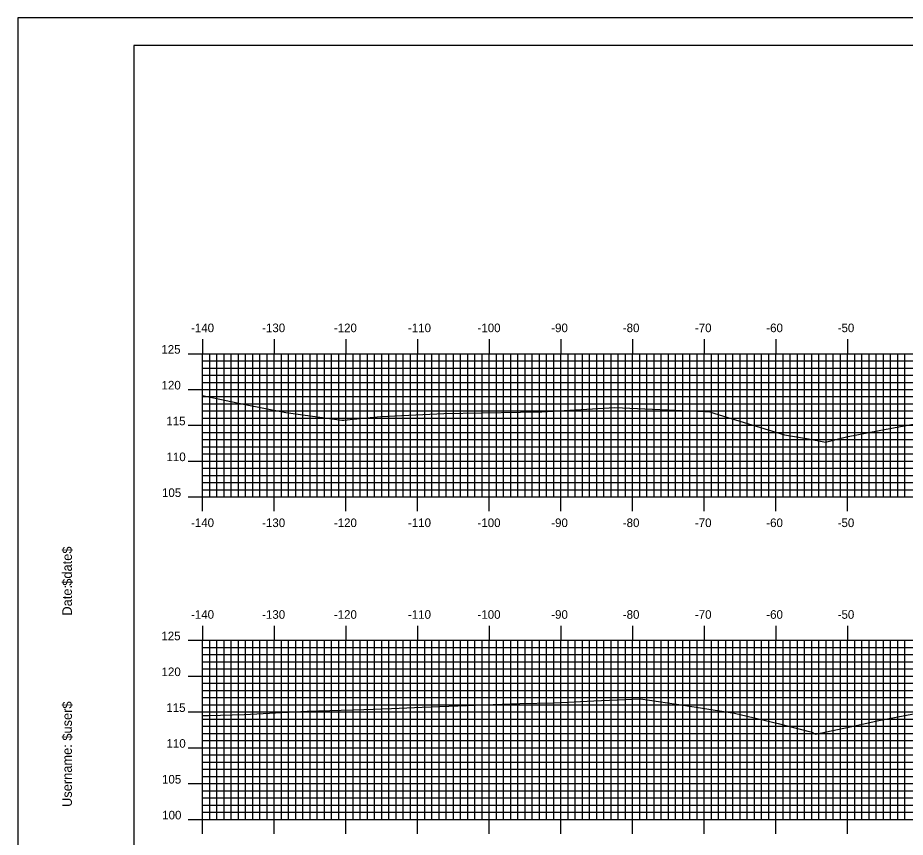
# Model space of a CAD drawing. Extents: x 1685586 to 1685929, y 461260 to 461480.
# Drawn here: x 1685586 to 1685709.8, y 461365.6 to 461480 of the extents above; entities that cross this region are included whole.
import ezdxf

# ---------------------------------------------------------------- set-up
doc = ezdxf.new("R2010")
doc.units = 0
for name, color, linetype in [('BORDER', 7, 'Continuous'), ('H_V ANNOTATION', 7, 'Continuous'), ('MAJOR', 7, 'Continuous'), ('MINOR', 7, 'Continuous'), ('PLOT BOUNDARY', 7, 'Continuous'), ('S_Roadway_Centerline', 7, 'Continuous')]:
    doc.layers.add(name, color=color, linetype=linetype)

msp = doc.modelspace()

# ---------------------------------------------------------------- linework, layer by layer
at = {"layer": 'BORDER'}
msp.add_lwpolyline([(1685602.14, 461266.07), (1685922.14, 461266.07), (1685922.14, 461476.07), (1685602.14, 461476.07)], close=True, dxfattribs=at)
at = {"layer": 'MAJOR'}
for p, q in [((1685611.74, 461435.08), (1685611.74, 461433.07)), ((1685621.74, 461435.08), (1685621.74, 461433.07)), ((1685631.74, 461435.08), (1685631.74, 461433.07)), ((1685641.74, 461435.08), (1685641.74, 461433.07)), ((1685651.74, 461435.08), (1685651.74, 461433.07)), ((1685661.74, 461435.08), (1685661.74, 461433.07)), ((1685671.74, 461435.08), (1685671.74, 461433.07)), ((1685681.74, 461435.08), (1685681.74, 461433.07)), ((1685691.74, 461435.08), (1685691.74, 461433.07)), ((1685701.74, 461435.08), (1685701.74, 461433.07)), ((1685609.74, 461433.07), (1685611.74, 461433.07)), ((1685611.74, 461433.07), (1685891.74, 461433.07)), ((1685611.74, 461413.07), (1685611.74, 461433.07)), ((1685611.74, 461413.07), (1685611.74, 461433.07)), ((1685611.74, 461433.07), (1685891.74, 461433.07)), ((1685621.74, 461413.07), (1685621.74, 461433.07)), ((1685631.74, 461413.07), (1685631.74, 461433.07)), ((1685641.74, 461413.07), (1685641.74, 461433.07)), ((1685651.74, 461413.07), (1685651.74, 461433.07)), ((1685661.74, 461413.07), (1685661.74, 461433.07)), ((1685671.74, 461413.07), (1685671.74, 461433.07)), ((1685681.74, 461413.07), (1685681.74, 461433.07)), ((1685691.74, 461413.07), (1685691.74, 461433.07)), ((1685701.74, 461413.07), (1685701.74, 461433.07)), ((1685609.74, 461428.07), (1685611.74, 461428.07)), ((1685611.74, 461428.07), (1685891.74, 461428.07)), ((1685609.74, 461423.07), (1685611.74, 461423.07)), ((1685611.74, 461423.07), (1685891.74, 461423.07)), ((1685609.74, 461418.07), (1685611.74, 461418.07)), ((1685611.74, 461418.07), (1685891.74, 461418.07)), ((1685609.74, 461413.07), (1685611.74, 461413.07)), ((1685611.74, 461413.07), (1685891.74, 461413.07)), ((1685611.74, 461413.07), (1685891.74, 461413.07)), ((1685611.74, 461411.07), (1685611.74, 461413.07)), ((1685621.74, 461411.07), (1685621.74, 461413.07)), ((1685631.74, 461411.07), (1685631.74, 461413.07)), ((1685641.74, 461411.07), (1685641.74, 461413.07)), ((1685651.74, 461411.07), (1685651.74, 461413.07)), ((1685661.74, 461411.07), (1685661.74, 461413.07)), ((1685671.74, 461411.07), (1685671.74, 461413.07)), ((1685681.74, 461411.07), (1685681.74, 461413.07)), ((1685691.74, 461411.07), (1685691.74, 461413.07)), ((1685701.74, 461411.07), (1685701.74, 461413.07)), ((1685611.74, 461395.08), (1685611.74, 461393.07)), ((1685621.74, 461395.08), (1685621.74, 461393.07)), ((1685631.74, 461395.08), (1685631.74, 461393.07)), ((1685641.74, 461395.08), (1685641.74, 461393.07)), ((1685651.74, 461395.08), (1685651.74, 461393.07)), ((1685661.74, 461395.08), (1685661.74, 461393.07)), ((1685671.74, 461395.08), (1685671.74, 461393.07)), ((1685681.74, 461395.08), (1685681.74, 461393.07)), ((1685691.74, 461395.08), (1685691.74, 461393.07)), ((1685701.74, 461395.08), (1685701.74, 461393.07)), ((1685609.74, 461393.07), (1685611.74, 461393.07)), ((1685611.74, 461393.07), (1685891.74, 461393.07)), ((1685611.74, 461368.07), (1685611.74, 461393.07)), ((1685611.74, 461368.07), (1685611.74, 461393.07)), ((1685611.74, 461393.07), (1685891.74, 461393.07)), ((1685621.74, 461368.07), (1685621.74, 461393.07)), ((1685631.74, 461368.07), (1685631.74, 461393.07)), ((1685641.74, 461368.07), (1685641.74, 461393.07)), ((1685651.74, 461368.07), (1685651.74, 461393.07)), ((1685661.74, 461368.07), (1685661.74, 461393.07)), ((1685671.74, 461368.07), (1685671.74, 461393.07)), ((1685681.74, 461368.07), (1685681.74, 461393.07)), ((1685691.74, 461368.07), (1685691.74, 461393.07)), ((1685701.74, 461368.07), (1685701.74, 461393.07)), ((1685609.74, 461388.07), (1685611.74, 461388.07)), ((1685611.74, 461388.07), (1685891.74, 461388.07)), ((1685609.74, 461383.07), (1685611.74, 461383.07)), ((1685611.74, 461383.07), (1685891.74, 461383.07)), ((1685609.74, 461378.07), (1685611.74, 461378.07)), ((1685611.74, 461378.07), (1685891.74, 461378.07)), ((1685609.74, 461373.07), (1685611.74, 461373.07)), ((1685611.74, 461373.07), (1685891.74, 461373.07)), ((1685609.74, 461368.07), (1685611.74, 461368.07)), ((1685611.74, 461368.07), (1685891.74, 461368.07)), ((1685611.74, 461368.07), (1685891.74, 461368.07)), ((1685611.74, 461366.07), (1685611.74, 461368.07)), ((1685621.74, 461366.07), (1685621.74, 461368.07)), ((1685631.74, 461366.07), (1685631.74, 461368.07)), ((1685641.74, 461366.07), (1685641.74, 461368.07)), ((1685651.74, 461366.07), (1685651.74, 461368.07)), ((1685661.74, 461366.07), (1685661.74, 461368.07)), ((1685671.74, 461366.07), (1685671.74, 461368.07)), ((1685681.74, 461366.07), (1685681.74, 461368.07)), ((1685691.74, 461366.07), (1685691.74, 461368.07)), ((1685701.74, 461366.07), (1685701.74, 461368.07))]:
    msp.add_line(p, q, dxfattribs=at)
at = {"layer": 'MINOR'}
for p, q in [((1685612.74, 461413.07), (1685612.74, 461433.07)), ((1685613.74, 461413.07), (1685613.74, 461433.07)), ((1685614.74, 461413.07), (1685614.74, 461433.07)), ((1685615.74, 461413.07), (1685615.74, 461433.07)), ((1685616.74, 461413.07), (1685616.74, 461433.07)), ((1685617.74, 461413.07), (1685617.74, 461433.07)), ((1685618.74, 461413.07), (1685618.74, 461433.07)), ((1685619.74, 461413.07), (1685619.74, 461433.07)), ((1685620.74, 461413.07), (1685620.74, 461433.07)), ((1685622.74, 461413.07), (1685622.74, 461433.07)), ((1685623.74, 461413.07), (1685623.74, 461433.07)), ((1685624.74, 461413.07), (1685624.74, 461433.07)), ((1685625.74, 461413.07), (1685625.74, 461433.07)), ((1685626.74, 461413.07), (1685626.74, 461433.07)), ((1685627.74, 461413.07), (1685627.74, 461433.07)), ((1685628.74, 461413.07), (1685628.74, 461433.07)), ((1685629.74, 461413.07), (1685629.74, 461433.07)), ((1685630.74, 461413.07), (1685630.74, 461433.07)), ((1685632.74, 461413.07), (1685632.74, 461433.07)), ((1685633.74, 461413.07), (1685633.74, 461433.07)), ((1685634.74, 461413.07), (1685634.74, 461433.07)), ((1685635.74, 461413.07), (1685635.74, 461433.07)), ((1685636.74, 461413.07), (1685636.74, 461433.07)), ((1685637.74, 461413.07), (1685637.74, 461433.07)), ((1685638.74, 461413.07), (1685638.74, 461433.07)), ((1685639.74, 461413.07), (1685639.74, 461433.07)), ((1685640.74, 461413.07), (1685640.74, 461433.07)), ((1685642.74, 461413.07), (1685642.74, 461433.07)), ((1685643.74, 461413.07), (1685643.74, 461433.07)), ((1685644.74, 461413.07), (1685644.74, 461433.07)), ((1685645.74, 461413.07), (1685645.74, 461433.07)), ((1685646.74, 461413.07), (1685646.74, 461433.07)), ((1685647.74, 461413.07), (1685647.74, 461433.07)), ((1685648.74, 461413.07), (1685648.74, 461433.07)), ((1685649.74, 461413.07), (1685649.74, 461433.07)), ((1685650.74, 461413.07), (1685650.74, 461433.07)), ((1685652.74, 461413.07), (1685652.74, 461433.07)), ((1685653.74, 461413.07), (1685653.74, 461433.07)), ((1685654.74, 461413.07), (1685654.74, 461433.07)), ((1685655.74, 461413.07), (1685655.74, 461433.07)), ((1685656.74, 461413.07), (1685656.74, 461433.07)), ((1685657.74, 461413.07), (1685657.74, 461433.07)), ((1685658.74, 461413.07), (1685658.74, 461433.07)), ((1685659.74, 461413.07), (1685659.74, 461433.07)), ((1685660.74, 461413.07), (1685660.74, 461433.07)), ((1685662.74, 461413.07), (1685662.74, 461433.07)), ((1685663.74, 461413.07), (1685663.74, 461433.07)), ((1685664.74, 461413.07), (1685664.74, 461433.07)), ((1685665.74, 461413.07), (1685665.74, 461433.07)), ((1685666.74, 461413.07), (1685666.74, 461433.07)), ((1685667.74, 461413.07), (1685667.74, 461433.07)), ((1685668.74, 461413.07), (1685668.74, 461433.07)), ((1685669.74, 461413.07), (1685669.74, 461433.07)), ((1685670.74, 461413.07), (1685670.74, 461433.07)), ((1685672.74, 461413.07), (1685672.74, 461433.07)), ((1685673.74, 461413.07), (1685673.74, 461433.07)), ((1685674.74, 461413.07), (1685674.74, 461433.07)), ((1685675.74, 461413.07), (1685675.74, 461433.07)), ((1685676.74, 461413.07), (1685676.74, 461433.07)), ((1685677.74, 461413.07), (1685677.74, 461433.07)), ((1685678.74, 461413.07), (1685678.74, 461433.07)), ((1685679.74, 461413.07), (1685679.74, 461433.07)), ((1685680.74, 461413.07), (1685680.74, 461433.07)), ((1685682.74, 461413.07), (1685682.74, 461433.07)), ((1685683.74, 461413.07), (1685683.74, 461433.07)), ((1685684.74, 461413.07), (1685684.74, 461433.07)), ((1685685.74, 461413.07), (1685685.74, 461433.07)), ((1685686.74, 461413.07), (1685686.74, 461433.07)), ((1685687.74, 461413.07), (1685687.74, 461433.07)), ((1685688.74, 461413.07), (1685688.74, 461433.07)), ((1685689.74, 461413.07), (1685689.74, 461433.07)), ((1685690.74, 461413.07), (1685690.74, 461433.07)), ((1685692.74, 461413.07), (1685692.74, 461433.07)), ((1685693.74, 461413.07), (1685693.74, 461433.07)), ((1685694.74, 461413.07), (1685694.74, 461433.07)), ((1685695.74, 461413.07), (1685695.74, 461433.07)), ((1685696.74, 461413.07), (1685696.74, 461433.07)), ((1685697.74, 461413.07), (1685697.74, 461433.07)), ((1685698.74, 461413.07), (1685698.74, 461433.07)), ((1685699.74, 461413.07), (1685699.74, 461433.07)), ((1685700.74, 461413.07), (1685700.74, 461433.07)), ((1685702.74, 461413.07), (1685702.74, 461433.07)), ((1685703.74, 461413.07), (1685703.74, 461433.07)), ((1685704.74, 461413.07), (1685704.74, 461433.07)), ((1685705.74, 461413.07), (1685705.74, 461433.07)), ((1685706.74, 461413.07), (1685706.74, 461433.07)), ((1685707.74, 461413.07), (1685707.74, 461433.07)), ((1685708.74, 461413.07), (1685708.74, 461433.07)), ((1685709.74, 461413.07), (1685709.74, 461433.07)), ((1685611.74, 461432.07), (1685891.74, 461432.07)), ((1685611.74, 461432.07), (1685613.75, 461432.07)), ((1685611.74, 461431.07), (1685891.74, 461431.07)), ((1685611.74, 461431.07), (1685613.75, 461431.07)), ((1685611.74, 461430.07), (1685891.74, 461430.07)), ((1685611.74, 461430.07), (1685613.75, 461430.07)), ((1685611.74, 461429.07), (1685891.74, 461429.07)), ((1685611.74, 461429.07), (1685613.75, 461429.07)), ((1685611.74, 461427.07), (1685891.74, 461427.07)), ((1685611.74, 461427.07), (1685613.75, 461427.07)), ((1685611.74, 461426.07), (1685891.74, 461426.07)), ((1685611.74, 461426.07), (1685613.75, 461426.07)), ((1685611.74, 461425.07), (1685891.74, 461425.07)), ((1685611.74, 461425.07), (1685613.75, 461425.07)), ((1685611.74, 461424.07), (1685891.74, 461424.07)), ((1685611.74, 461424.07), (1685613.75, 461424.07)), ((1685611.74, 461422.07), (1685891.74, 461422.07)), ((1685611.74, 461422.07), (1685613.75, 461422.07)), ((1685611.74, 461421.07), (1685891.74, 461421.07)), ((1685611.74, 461421.07), (1685613.75, 461421.07)), ((1685611.74, 461420.07), (1685891.74, 461420.07)), ((1685611.74, 461420.07), (1685613.75, 461420.07)), ((1685611.74, 461419.07), (1685891.74, 461419.07)), ((1685611.74, 461419.07), (1685613.75, 461419.07)), ((1685611.74, 461417.07), (1685891.74, 461417.07)), ((1685611.74, 461417.07), (1685613.75, 461417.07)), ((1685611.74, 461416.07), (1685891.74, 461416.07)), ((1685611.74, 461416.07), (1685613.75, 461416.07)), ((1685611.74, 461415.07), (1685891.74, 461415.07)), ((1685611.74, 461415.07), (1685613.75, 461415.07)), ((1685611.74, 461414.07), (1685891.74, 461414.07)), ((1685611.74, 461414.07), (1685613.75, 461414.07)), ((1685612.74, 461368.07), (1685612.74, 461393.07)), ((1685613.74, 461368.07), (1685613.74, 461393.07)), ((1685614.74, 461368.07), (1685614.74, 461393.07)), ((1685615.74, 461368.07), (1685615.74, 461393.07)), ((1685616.74, 461368.07), (1685616.74, 461393.07)), ((1685617.74, 461368.07), (1685617.74, 461393.07)), ((1685618.74, 461368.07), (1685618.74, 461393.07)), ((1685619.74, 461368.07), (1685619.74, 461393.07)), ((1685620.74, 461368.07), (1685620.74, 461393.07)), ((1685622.74, 461368.07), (1685622.74, 461393.07)), ((1685623.74, 461368.07), (1685623.74, 461393.07)), ((1685624.74, 461368.07), (1685624.74, 461393.07)), ((1685625.74, 461368.07), (1685625.74, 461393.07)), ((1685626.74, 461368.07), (1685626.74, 461393.07)), ((1685627.74, 461368.07), (1685627.74, 461393.07)), ((1685628.74, 461368.07), (1685628.74, 461393.07)), ((1685629.74, 461368.07), (1685629.74, 461393.07)), ((1685630.74, 461368.07), (1685630.74, 461393.07)), ((1685632.74, 461368.07), (1685632.74, 461393.07)), ((1685633.74, 461368.07), (1685633.74, 461393.07)), ((1685634.74, 461368.07), (1685634.74, 461393.07)), ((1685635.74, 461368.07), (1685635.74, 461393.07)), ((1685636.74, 461368.07), (1685636.74, 461393.07)), ((1685637.74, 461368.07), (1685637.74, 461393.07)), ((1685638.74, 461368.07), (1685638.74, 461393.07)), ((1685639.74, 461368.07), (1685639.74, 461393.07)), ((1685640.74, 461368.07), (1685640.74, 461393.07)), ((1685642.74, 461368.07), (1685642.74, 461393.07)), ((1685643.74, 461368.07), (1685643.74, 461393.07)), ((1685644.74, 461368.07), (1685644.74, 461393.07)), ((1685645.74, 461368.07), (1685645.74, 461393.07)), ((1685646.74, 461368.07), (1685646.74, 461393.07)), ((1685647.74, 461368.07), (1685647.74, 461393.07)), ((1685648.74, 461368.07), (1685648.74, 461393.07)), ((1685649.74, 461368.07), (1685649.74, 461393.07)), ((1685650.74, 461368.07), (1685650.74, 461393.07)), ((1685652.74, 461368.07), (1685652.74, 461393.07)), ((1685653.74, 461368.07), (1685653.74, 461393.07)), ((1685654.74, 461368.07), (1685654.74, 461393.07)), ((1685655.74, 461368.07), (1685655.74, 461393.07)), ((1685656.74, 461368.07), (1685656.74, 461393.07)), ((1685657.74, 461368.07), (1685657.74, 461393.07)), ((1685658.74, 461368.07), (1685658.74, 461393.07)), ((1685659.74, 461368.07), (1685659.74, 461393.07)), ((1685660.74, 461368.07), (1685660.74, 461393.07)), ((1685662.74, 461368.07), (1685662.74, 461393.07)), ((1685663.74, 461368.07), (1685663.74, 461393.07)), ((1685664.74, 461368.07), (1685664.74, 461393.07)), ((1685665.74, 461368.07), (1685665.74, 461393.07)), ((1685666.74, 461368.07), (1685666.74, 461393.07)), ((1685667.74, 461368.07), (1685667.74, 461393.07)), ((1685668.74, 461368.07), (1685668.74, 461393.07)), ((1685669.74, 461368.07), (1685669.74, 461393.07)), ((1685670.74, 461368.07), (1685670.74, 461393.07)), ((1685672.74, 461368.07), (1685672.74, 461393.07)), ((1685673.74, 461368.07), (1685673.74, 461393.07)), ((1685674.74, 461368.07), (1685674.74, 461393.07)), ((1685675.74, 461368.07), (1685675.74, 461393.07)), ((1685676.74, 461368.07), (1685676.74, 461393.07)), ((1685677.74, 461368.07), (1685677.74, 461393.07)), ((1685678.74, 461368.07), (1685678.74, 461393.07)), ((1685679.74, 461368.07), (1685679.74, 461393.07)), ((1685680.74, 461368.07), (1685680.74, 461393.07)), ((1685682.74, 461368.07), (1685682.74, 461393.07)), ((1685683.74, 461368.07), (1685683.74, 461393.07)), ((1685684.74, 461368.07), (1685684.74, 461393.07)), ((1685685.74, 461368.07), (1685685.74, 461393.07)), ((1685686.74, 461368.07), (1685686.74, 461393.07)), ((1685687.74, 461368.07), (1685687.74, 461393.07)), ((1685688.74, 461368.07), (1685688.74, 461393.07)), ((1685689.74, 461368.07), (1685689.74, 461393.07)), ((1685690.74, 461368.07), (1685690.74, 461393.07)), ((1685692.74, 461368.07), (1685692.74, 461393.07)), ((1685693.74, 461368.07), (1685693.74, 461393.07)), ((1685694.74, 461368.07), (1685694.74, 461393.07)), ((1685695.74, 461368.07), (1685695.74, 461393.07)), ((1685696.74, 461368.07), (1685696.74, 461393.07)), ((1685697.74, 461368.07), (1685697.74, 461393.07)), ((1685698.74, 461368.07), (1685698.74, 461393.07)), ((1685699.74, 461368.07), (1685699.74, 461393.07)), ((1685700.74, 461368.07), (1685700.74, 461393.07)), ((1685702.74, 461368.07), (1685702.74, 461393.07)), ((1685703.74, 461368.07), (1685703.74, 461393.07)), ((1685704.74, 461368.07), (1685704.74, 461393.07)), ((1685705.74, 461368.07), (1685705.74, 461393.07)), ((1685706.74, 461368.07), (1685706.74, 461393.07)), ((1685707.74, 461368.07), (1685707.74, 461393.07)), ((1685708.74, 461368.07), (1685708.74, 461393.07)), ((1685709.74, 461368.07), (1685709.74, 461393.07)), ((1685611.74, 461392.07), (1685891.74, 461392.07)), ((1685611.74, 461392.07), (1685613.75, 461392.07)), ((1685611.74, 461391.07), (1685891.74, 461391.07)), ((1685611.74, 461391.07), (1685613.75, 461391.07)), ((1685611.74, 461390.07), (1685891.74, 461390.07)), ((1685611.74, 461390.07), (1685613.75, 461390.07)), ((1685611.74, 461389.07), (1685891.74, 461389.07)), ((1685611.74, 461389.07), (1685613.75, 461389.07)), ((1685611.74, 461387.07), (1685891.74, 461387.07)), ((1685611.74, 461387.07), (1685613.75, 461387.07)), ((1685611.74, 461386.07), (1685891.74, 461386.07)), ((1685611.74, 461386.07), (1685613.75, 461386.07)), ((1685611.74, 461385.07), (1685891.74, 461385.07)), ((1685611.74, 461385.07), (1685613.75, 461385.07)), ((1685611.74, 461384.07), (1685891.74, 461384.07)), ((1685611.74, 461384.07), (1685613.75, 461384.07)), ((1685611.74, 461382.07), (1685891.74, 461382.07)), ((1685611.74, 461382.07), (1685613.75, 461382.07)), ((1685611.74, 461381.07), (1685891.74, 461381.07)), ((1685611.74, 461381.07), (1685613.75, 461381.07)), ((1685611.74, 461380.07), (1685891.74, 461380.07)), ((1685611.74, 461380.07), (1685613.75, 461380.07)), ((1685611.74, 461379.07), (1685891.74, 461379.07)), ((1685611.74, 461379.07), (1685613.75, 461379.07)), ((1685611.74, 461377.07), (1685891.74, 461377.07)), ((1685611.74, 461377.07), (1685613.75, 461377.07)), ((1685611.74, 461376.07), (1685891.74, 461376.07)), ((1685611.74, 461376.07), (1685613.75, 461376.07)), ((1685611.74, 461375.07), (1685891.74, 461375.07)), ((1685611.74, 461375.07), (1685613.75, 461375.07)), ((1685611.74, 461374.07), (1685891.74, 461374.07)), ((1685611.74, 461374.07), (1685613.75, 461374.07)), ((1685611.74, 461372.07), (1685891.74, 461372.07)), ((1685611.74, 461372.07), (1685613.75, 461372.07)), ((1685611.74, 461371.07), (1685891.74, 461371.07)), ((1685611.74, 461371.07), (1685613.75, 461371.07)), ((1685611.74, 461370.07), (1685891.74, 461370.07)), ((1685611.74, 461370.07), (1685613.75, 461370.07)), ((1685611.74, 461369.07), (1685891.74, 461369.07)), ((1685611.74, 461369.07), (1685613.75, 461369.07))]:
    msp.add_line(p, q, dxfattribs=at)
at = {"layer": 'PLOT BOUNDARY'}
msp.add_lwpolyline([(1685585.96, 461259.95), (1685925.96, 461259.95), (1685925.96, 461479.95), (1685585.96, 461479.95)], close=True, dxfattribs=at)
at = {"layer": 'S_Roadway_Centerline'}
for points in [[(1685611.74, 461427.25), (1685617.45, 461426.01), (1685623.36, 461424.87), (1685631.18, 461423.8), (1685631.47, 461423.81), (1685634.16, 461424.06), (1685636.63, 461424.28), (1685645.4, 461424.73), (1685656.09, 461424.9), (1685657.75, 461424.94), (1685659.07, 461424.97), (1685669.28, 461425.55), (1685681.85, 461424.99), (1685682.52, 461424.94), (1685683.2, 461424.74), (1685692.94, 461421.74), (1685696.27, 461421.17), (1685698.67, 461420.72), (1685701.58, 461421.45), (1685706.16, 461422.36), (1685717.62, 461424.47)], [(1685611.74, 461382.55), (1685612.56, 461382.58), (1685617.54, 461382.73), (1685626.33, 461383.19), (1685634.25, 461383.39), (1685638.12, 461383.53), (1685642.4, 461383.74), (1685656, 461384.25), (1685660.81, 461384.36), (1685666.34, 461384.62), (1685672.82, 461384.89), (1685679.12, 461383.99), (1685685.95, 461382.92), (1685692.05, 461381.47), (1685696.18, 461380.39), (1685696.63, 461380.29), (1685697.26, 461379.98), (1685702.74, 461381.15), (1685705.87, 461381.82), (1685710.94, 461382.8)]]:
    msp.add_lwpolyline(points, dxfattribs=at)

# ---------------------------------------------------------------- texts
at = {"layer": 'BORDER'}
for s, p in [('$date$', (1685593.51, 461400.68)), ('Date:', (1685593.51, 461396.51)), ('$user$', (1685593.51, 461379.06)), ('Username:', (1685593.51, 461369.81))]:
    msp.add_text(s, height=1.339, rotation=90, dxfattribs=at).set_placement(p)
at = {"layer": 'H_V ANNOTATION'}
for s, p in [('-140', (1685610.13, 461436.07)), ('-130', (1685620.05, 461436.07)), ('-120', (1685630.06, 461436.07)), ('-110', (1685640.4, 461436.07)), ('-100', (1685650.1, 461436.07)), ('-90', (1685660.39, 461436.07)), ('-80', (1685670.37, 461436.07)), ('-70', (1685680.43, 461436.07)), ('-60', (1685690.39, 461436.07)), ('-50', (1685700.35, 461436.07)), ('125', (1685605.99, 461433.07)), ('120', (1685606.02, 461428.07)), ('115', (1685606.68, 461423.07)), ('110', (1685606.71, 461418.07)), ('105', (1685606.08, 461413.07)), ('-140', (1685610.13, 461408.87)), ('-130', (1685620.05, 461408.87)), ('-120', (1685630.06, 461408.87)), ('-110', (1685640.4, 461408.87)), ('-100', (1685650.1, 461408.87)), ('-90', (1685660.39, 461408.87)), ('-80', (1685670.37, 461408.87)), ('-70', (1685680.43, 461408.87)), ('-60', (1685690.39, 461408.87)), ('-50', (1685700.35, 461408.87)), ('-140', (1685610.13, 461396.07)), ('-130', (1685620.05, 461396.07)), ('-120', (1685630.06, 461396.07)), ('-110', (1685640.4, 461396.07)), ('-100', (1685650.1, 461396.07)), ('-90', (1685660.39, 461396.07)), ('-80', (1685670.37, 461396.07)), ('-70', (1685680.43, 461396.07)), ('-60', (1685690.39, 461396.07)), ('-50', (1685700.35, 461396.07)), ('125', (1685605.99, 461393.07)), ('120', (1685606.02, 461388.07)), ('115', (1685606.68, 461383.07)), ('110', (1685606.71, 461378.07)), ('105', (1685606.08, 461373.07)), ('100', (1685606.11, 461368.07))]:
    msp.add_text(s, height=1.2, dxfattribs=at).set_placement(p)
at = {"layer": 'MAJOR'}
for p in [(1685611.73, 461413.07), (1685611.73, 461368.07)]:
    msp.add_text('-', height=0.012, dxfattribs=at).set_placement(p)

doc.saveas('drawing.dxf')
